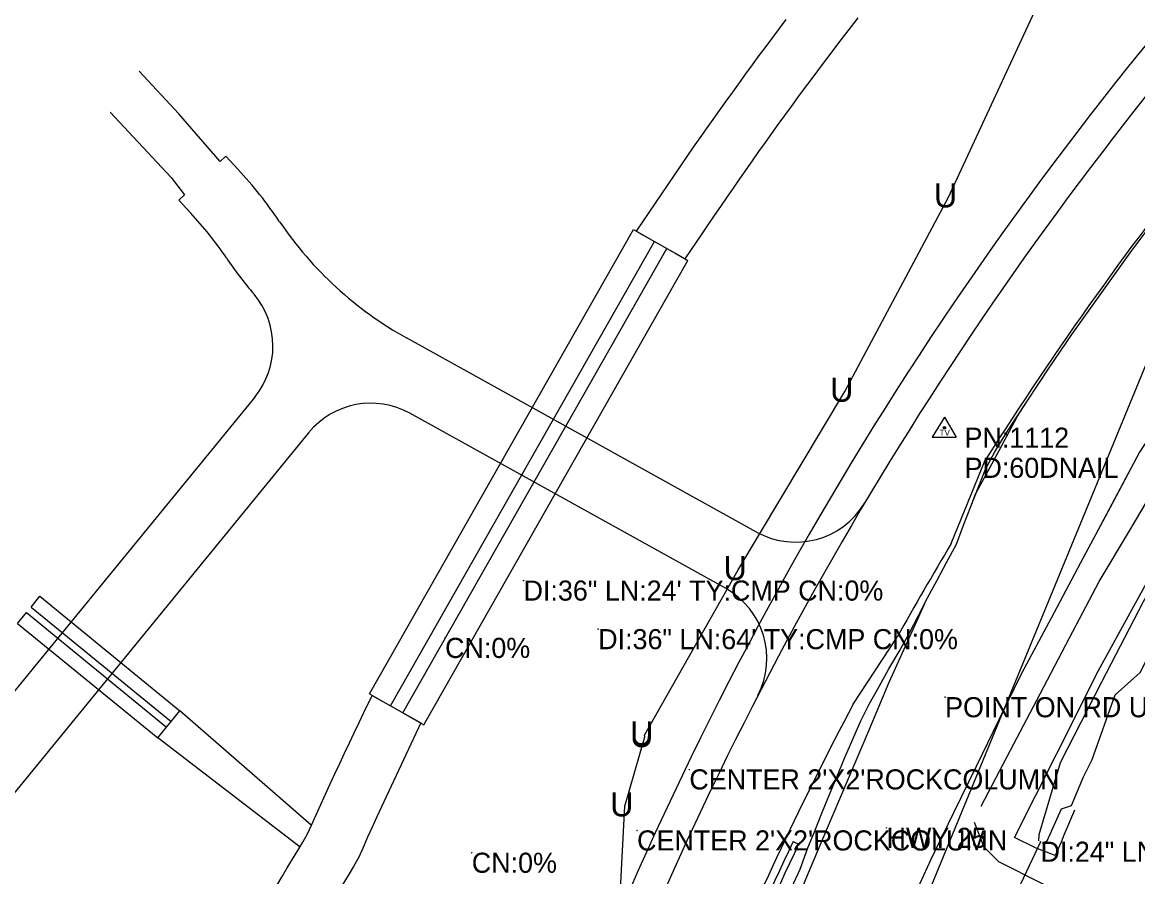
# Model space of a CAD drawing. Extents: x 1282810 to 1284464, y 402460 to 405899.
# Drawn here: x 1283356.5 to 1283634, y 404254.3 to 404466.8 of the extents above; entities that cross this region are included whole.
import ezdxf

# ---------------------------------------------------------------- set-up
doc = ezdxf.new("R2010")
doc.units = 0
for name, color, linetype in [('Default', 7, 'Continuous'), ('MOT_Drainage_Stage 2', 7, 'Continuous'), ('MOT_Driveway_Stage 2', 7, 'Continuous'), ('MOT_Proposed Road_Stage 2', 7, 'Continuous'), ('MOT_Shld_Stage 2', 7, 'Continuous'), ('MOT_Stage 1_Conc Ditch Paving', 7, 'Continuous'), ('MOT_Stage 2_Retaining Wall', 7, 'Continuous'), ('R_Conc Ditch Paving', 7, 'Continuous'), ('R_Drainage', 7, 'Continuous'), ('S_BASELINE', 7, 'Continuous'), ('S_CROSS_DRAIN', 7, 'Continuous'), ('S_CROSS_DRAIN_ANNOT', 7, 'Continuous'), ('S_DITCHLINE', 7, 'Continuous'), ('S_DRG_PT_SYM', 7, 'Continuous'), ('S_EDGE_CONCRETE', 7, 'Continuous'), ('S_EDGE_PAVEMENT', 7, 'Continuous'), ('S_MISC_STRUCTURES_ANNOT', 7, 'Continuous'), ('S_MSC_PT_SYM', 7, 'Continuous'), ('S_SECONDARY_CTL', 7, 'Continuous'), ('S_SECONDARY_CTL_ANNOT', 7, 'Continuous'), ('S_SHOULDER', 7, 'Continuous'), ('S_SURVEY_TEXT_ANNOT', 7, 'Continuous'), ('S_UNDERGROUND_CABLE', 7, 'Continuous'), ('S_UTL_PT_SYM', 7, 'Continuous')]:
    doc.layers.add(name, color=color, linetype=linetype)

msp = doc.modelspace()

# ---------------------------------------------------------------- linework, layer by layer
at = {"layer": 'MOT_Drainage_Stage 2'}
for p, q in [((1283442.9, 404299.75), (1283508.57, 404415.27)), ((1283508.57, 404415.27), (1283513.78, 404412.3)), ((1283448.12, 404296.78), (1283513.78, 404412.3)), ((1283451.16, 404295.05), (1283516.82, 404410.57)), ((1283516.82, 404410.57), (1283518.5, 404409.62)), ((1283518.79, 404409.46), (1283522.04, 404407.61)), ((1283456.38, 404292.09), (1283522.04, 404407.61)), ((1283442.9, 404299.75), (1283448.12, 404296.78)), ((1283451.16, 404295.05), (1283456.38, 404292.09))]:
    msp.add_line(p, q, dxfattribs=at)
at = {"layer": 'MOT_Driveway_Stage 2'}
for p, q in [((1283407.12, 404433.51), (1283405.74, 404432.23)), ((1283410.13, 404430.28), (1283407.12, 404433.51)), ((1283396.86, 404423.96), (1283395.41, 404422.62)), ((1283398.41, 404419.39), (1283395.41, 404422.62)), ((1283539.17, 404340.02), (1283452.1, 404388.31)), ((1283414.32, 404373.62), (1283274.79, 404202.97)), ((1283531.41, 404326.02), (1283452.91, 404369.57)), ((1283427.73, 404364.74), (1283287.18, 404192.85))]:
    msp.add_line(p, q, dxfattribs=at)
for centre, radius, start, end in [((1283331.05, 404356.72), 108, 34.0718, 42.9327), ((1283331.05, 404356.72), 92, 34.0718, 42.9327), ((1283496.72, 404468.77), 92, 214.0718, 240.9844), ((1283496.72, 404468.77), 108, 214.0718, 220.1219), ((1283398.84, 404386.28), 20, 320.7283, 40.1219), ((1283443.21, 404352.08), 20, 60.9844, 140.7283), ((1283548.87, 404357.51), 20, 240.9844, 329.2507), ((1283521.71, 404308.53), 20, 332.7181, 60.9844)]:
    msp.add_arc(centre, radius, start, end, dxfattribs=at)
at = {"layer": 'MOT_Proposed Road_Stage 2'}
for p, q in [((1283587.59, 404337.18), (1283596.03, 404357.88)), ((1283563.16, 404297.18), (1283574.13, 404313.88))]:
    msp.add_line(p, q, dxfattribs=at)
msp.add_lwpolyline([(1283718.07, 404476.36), (1283708.96, 404465.16), (1283699.85, 404453.97), (1283691.43, 404442.7), (1283683.01, 404431.44), (1283674.6, 404420.17), (1283666.18, 404408.91), (1283658.24, 404396.65), (1283650.31, 404384.4), (1283642.37, 404372.14), (1283634.44, 404359.89), (1283623.48, 404339.36)], dxfattribs=at)
for radius, start, end in [(905.47, 138.45801, 157.33333), (885.47, 141.27466, 147.66939), (881.81, 149.09939, 150.84794), (883.47, 152.14026, 157.33333)]:
    msp.add_arc((1284344.24, 403884.33), radius, start, end, dxfattribs=at)
at = {"layer": 'MOT_Shld_Stage 2'}
msp.add_arc((1284344.24, 403884.33), 913.47, 136.3373, 157.33333, dxfattribs=at)
at = {"layer": 'MOT_Stage 1_Conc Ditch Paving'}
for p, q in [((1283509.17, 404414.92), (1283521.39, 404407.98)), ((1283443.54, 404299.39), (1283455.61, 404292.52))]:
    msp.add_line(p, q, dxfattribs=at)
for points in [[(1283546.46, 404467.54), (1283544.77, 404465.3), (1283543.09, 404463.06), (1283541.42, 404460.81), (1283539.75, 404458.56), (1283538.08, 404456.3), (1283536.43, 404454.04), (1283534.78, 404451.77), (1283533.13, 404449.5), (1283531.5, 404447.22), (1283529.87, 404444.94), (1283528.24, 404442.65), (1283526.62, 404440.36), (1283525.01, 404438.07), (1283523.41, 404435.77), (1283521.81, 404433.46), (1283520.21, 404431.16), (1283518.63, 404428.85), (1283517.04, 404426.53), (1283515.46, 404424.21), (1283509.17, 404414.92)], [(1283521.39, 404407.98), (1283525.58, 404414.19), (1283527.13, 404416.48), (1283528.69, 404418.76), (1283530.25, 404421.05), (1283531.82, 404423.33), (1283533.39, 404425.61), (1283534.97, 404427.88), (1283536.55, 404430.15), (1283538.14, 404432.41), (1283539.74, 404434.67), (1283541.34, 404436.92), (1283542.95, 404439.17), (1283544.56, 404441.41), (1283546.18, 404443.65), (1283547.81, 404445.89), (1283549.44, 404448.12), (1283551.08, 404450.34), (1283552.73, 404452.56), (1283554.38, 404454.78), (1283556.04, 404456.99), (1283557.7, 404459.2), (1283559.37, 404461.4), (1283561.05, 404463.6), (1283562.73, 404465.79), (1283564.42, 404467.98)], [(1283419.78, 404252.12), (1283421.1, 404254.28), (1283422.42, 404256.44), (1283423.74, 404258.6), (1283425.05, 404260.76), (1283426.32, 404262.83), (1283427.4, 404264.9), (1283428.41, 404267.11), (1283429.57, 404269.67), (1283430.74, 404272.23), (1283431.91, 404274.79), (1283433.09, 404277.34), (1283434.27, 404279.9), (1283435.46, 404282.45), (1283436.66, 404284.99), (1283437.86, 404287.54), (1283439.06, 404290.08), (1283440.27, 404292.61), (1283441.49, 404295.15), (1283443.54, 404299.39)], [(1283455.61, 404292.52), (1283447.05, 404274.18), (1283445.88, 404271.66), (1283444.71, 404269.14), (1283443.56, 404266.61), (1283442.4, 404264.08), (1283441.26, 404261.55), (1283440.17, 404259.17), (1283438.92, 404256.79), (1283437.56, 404254.55), (1283436.24, 404252.39)]]:
    msp.add_lwpolyline(points, dxfattribs=at)
at = {"layer": 'MOT_Stage 2_Retaining Wall'}
msp.add_line((1283548.24, 404262.99), (1283549.59, 404262.34), dxfattribs=at)
for radius in [881.47, 879.97]:
    msp.add_arc((1284344.24, 403884.33), radius, 154.55939, 157.33333, dxfattribs=at)
at = {"layer": 'R_Conc Ditch Paving'}
for p, q in [((1283428.39, 404267.07), (1283395.71, 404295.56)), ((1283392.39, 404291.5), (1283393.49, 404292.85)), ((1283425.58, 404261.61), (1283390.17, 404288.79))]:
    msp.add_line(p, q, dxfattribs=at)
at = {"layer": 'R_Drainage'}
for p, q in [((1283358.66, 404321.34), (1283360.87, 404324.05)), ((1283360.87, 404324.05), (1283395.71, 404295.56)), ((1283355.33, 404317.27), (1283357.55, 404319.98)), ((1283357.55, 404319.98), (1283392.39, 404291.5)), ((1283358.66, 404321.34), (1283393.49, 404292.85)), ((1283355.33, 404317.27), (1283390.17, 404288.79)), ((1283393.49, 404292.85), (1283395.71, 404295.56)), ((1283390.17, 404288.79), (1283392.39, 404291.5))]:
    msp.add_line(p, q, dxfattribs=at)
at = {"layer": 'S_BASELINE'}
msp.add_line((1283396.79, 403800.11), (1283700.58, 404538.68), dxfattribs=at)
at = {"layer": 'S_CROSS_DRAIN'}
msp.add_line((1283609.78, 404262.98), (1283595.99, 404233.83), dxfattribs=at)
at = {"layer": 'S_DITCHLINE'}
for points in [[(1283609.36, 404263.21), (1283609.41, 404264.74), (1283614.77, 404282.66), (1283625.07, 404302.72), (1283635.38, 404322.78), (1283642.15, 404334.45), (1283648.92, 404346.13), (1283655.69, 404357.8), (1283662.46, 404369.47), (1283670.31, 404381.63), (1283678.16, 404393.78), (1283686, 404405.93), (1283693.85, 404418.09), (1283702.42, 404428.99), (1283710.99, 404439.89), (1283719.56, 404450.8), (1283728.14, 404461.7), (1283737.59, 404472.54)], [(1283610.29, 404262.6), (1283611.47, 404263.21), (1283614.97, 404271.12), (1283617.46, 404271.95), (1283620.45, 404279.13), (1283622.59, 404283.42), (1283628.37, 404299.55), (1283634.55, 404305.06), (1283644.21, 404323.84), (1283653.88, 404342.62), (1283663.81, 404358.58), (1283673.75, 404374.54), (1283683.07, 404383.99), (1283693.03, 404405.26), (1283703.98, 404420.61), (1283715.07, 404431.72), (1283723.5, 404444.12), (1283731.94, 404456.53), (1283742.27, 404467.67)]]:
    msp.add_lwpolyline(points, dxfattribs=at)
at = {"layer": 'S_DRG_PT_SYM'}
for points in [[(1283481.19, 404327.96), (1283481.19, 404328.01), (1283481.19, 404327.96), (1283481.14, 404327.96), (1283481.19, 404327.96), (1283481.19, 404327.91), (1283481.19, 404327.96), (1283481.24, 404327.96)], [(1283461.66, 404313.69), (1283461.66, 404313.74), (1283461.66, 404313.69), (1283461.61, 404313.69), (1283461.66, 404313.69), (1283461.66, 404313.64), (1283461.66, 404313.69), (1283461.71, 404313.69)], [(1283499.75, 404315.87), (1283499.75, 404315.92), (1283499.75, 404315.87), (1283499.7, 404315.87), (1283499.75, 404315.87), (1283499.75, 404315.82), (1283499.75, 404315.87), (1283499.8, 404315.87)], [(1283609.78, 404262.98), (1283609.78, 404263.03), (1283609.78, 404262.98), (1283609.73, 404262.98), (1283609.78, 404262.98), (1283609.78, 404262.93), (1283609.78, 404262.98), (1283609.83, 404262.98)], [(1283468.31, 404260.24), (1283468.31, 404260.29), (1283468.31, 404260.24), (1283468.26, 404260.24), (1283468.31, 404260.24), (1283468.31, 404260.19), (1283468.31, 404260.24), (1283468.36, 404260.24)]]:
    msp.add_lwpolyline(points, dxfattribs=at)
at = {"layer": 'S_EDGE_CONCRETE'}
msp.add_lwpolyline([(1283618.25, 404270.79), (1283615.62, 404264.61), (1283614.91, 404262.89), (1283613.43, 404259.58), (1283608.69, 404261.34), (1283603.27, 404264.04), (1283613.73, 404284.79), (1283624.19, 404305.55), (1283635.7, 404326.58), (1283647.2, 404347.61), (1283653.8, 404358.29), (1283660.4, 404368.97), (1283667, 404379.65), (1283673.6, 404390.33), (1283681.18, 404401.41), (1283688.76, 404412.48), (1283696.34, 404423.56), (1283703.92, 404434.64), (1283719.6, 404453.87), (1283735.28, 404473.1)], dxfattribs=at)
at = {"layer": 'S_EDGE_PAVEMENT'}
for points in [[(1283405.74, 404432.23), (1283395.47, 404444.08), (1283385.55, 404454.66)], [(1283378.38, 404444.49), (1283393.51, 404428.27), (1283396.86, 404423.96)], [(1283603.85, 404368.64), (1283606.42, 404372.59), (1283609.17, 404376.76), (1283611.96, 404380.9), (1283614.76, 404385.04), (1283617.6, 404389.15), (1283620.47, 404393.24), (1283623.35, 404397.32), (1283626.24, 404401.4), (1283629.16, 404405.45), (1283632.11, 404409.48), (1283635.09, 404413.5), (1283638.09, 404417.49), (1283641.14, 404421.45), (1283644.2, 404425.39), (1283647.29, 404429.32), (1283648.41, 404430.76)], [(1283603.85, 404368.64), (1283598.14, 404357.93), (1283593.73, 404349.67)], [(1283634.44, 404359.89), (1283627.09, 404346.13), (1283619.74, 404332.37), (1283612.4, 404318.61), (1283605.05, 404304.85), (1283599.42, 404293.28), (1283593.79, 404281.72), (1283588.16, 404270.15), (1283582.53, 404258.59), (1283576.15, 404244.59), (1283569.76, 404230.6), (1283563.51, 404216.22), (1283557.25, 404201.83), (1283551, 404187.45), (1283544.75, 404173.06), (1283538.9, 404159.19), (1283533.05, 404145.32), (1283527.2, 404131.45), (1283521.35, 404117.58), (1283514.89, 404102.6), (1283508.43, 404087.61), (1283501.97, 404072.63), (1283495.51, 404057.64)], [(1283580.91, 404322.16), (1283581.69, 404323.67), (1283584.04, 404328.08), (1283586.43, 404332.47), (1283588.86, 404337.04), (1283590.63, 404341.72), (1283592.43, 404346.38), (1283593.73, 404349.67)], [(1283580.91, 404322.16), (1283572.08, 404302.57), (1283566.88, 404290.31), (1283561.68, 404278.06), (1283556.49, 404265.8), (1283551.29, 404253.55), (1283545.42, 404239.1), (1283539.55, 404224.64), (1283533.68, 404210.19), (1283527.81, 404195.74), (1283522.03, 404181.72), (1283516.25, 404167.7), (1283510.47, 404153.68), (1283504.7, 404139.66), (1283498.96, 404125.92), (1283493.22, 404112.18), (1283487.49, 404098.44), (1283481.75, 404084.71), (1283475.3, 404069.12), (1283468.85, 404053.54)], [(1283593.24, 404267.8), (1283595.7, 404261.72), (1283599.33, 404258.06), (1283610.19, 404252.56), (1283628.07, 404243.86), (1283641.66, 404237.19), (1283635.3, 404223.5), (1283614.86, 404231.99), (1283600.63, 404239.28), (1283592.76, 404242.6), (1283586.77, 404243.11), (1283580.86, 404240.13)]]:
    msp.add_lwpolyline(points, dxfattribs=at)
at = {"layer": 'S_MSC_PT_SYM'}
for points in [[(1283586.05, 404298.94), (1283586.05, 404298.99), (1283586.05, 404298.94), (1283586, 404298.94), (1283586.05, 404298.94), (1283586.05, 404298.89), (1283586.05, 404298.94), (1283586.1, 404298.94)], [(1283522.42, 404280.98), (1283522.42, 404281.03), (1283522.42, 404280.98), (1283522.37, 404280.98), (1283522.42, 404280.98), (1283522.42, 404280.93), (1283522.42, 404280.98), (1283522.47, 404280.98)], [(1283571.49, 404266.44), (1283571.49, 404266.49), (1283571.49, 404266.44), (1283571.44, 404266.44), (1283571.49, 404266.44), (1283571.49, 404266.39), (1283571.49, 404266.44), (1283571.54, 404266.44)], [(1283509.42, 404265.79), (1283509.42, 404265.84), (1283509.42, 404265.79), (1283509.37, 404265.79), (1283509.42, 404265.79), (1283509.42, 404265.74), (1283509.42, 404265.79), (1283509.47, 404265.79)]]:
    msp.add_lwpolyline(points, dxfattribs=at)
at = {"layer": 'S_SECONDARY_CTL'}
for p, q in [((1283585.88, 404368.61), (1283582.87, 404363.65)), ((1283585.88, 404368.61), (1283588.83, 404363.65)), ((1283582.87, 404363.65), (1283588.83, 404363.65))]:
    msp.add_line(p, q, dxfattribs=at)
for radius in [0.311, 0.183, 0.103]:
    msp.add_circle((1283585.88, 404366), radius, dxfattribs=at)
at = {"layer": 'S_SHOULDER'}
for points in [[(1283594.98, 404271.8), (1283602.33, 404285.78), (1283609.68, 404299.75), (1283617.03, 404313.73), (1283624.38, 404327.7), (1283632.14, 404340.73), (1283639.89, 404353.76), (1283647.64, 404366.78), (1283655.39, 404379.81), (1283664.59, 404393.03), (1283673.79, 404406.25), (1283682.99, 404419.46), (1283692.19, 404432.68), (1283701.44, 404444.15), (1283710.69, 404455.61), (1283719.93, 404467.08)], [(1283551.94, 404261.42), (1283553.53, 404265.46), (1283555.39, 404270.09), (1283557.27, 404274.7), (1283559.18, 404279.31), (1283561.11, 404283.9), (1283563.1, 404288.48), (1283565.09, 404293.05), (1283567.17, 404297.23), (1283569.62, 404301.61), (1283572.07, 404305.98), (1283574.62, 404310.28), (1283577.11, 404314.8), (1283579.39, 404319.24), (1283581.69, 404323.67), (1283584.04, 404328.08), (1283586.43, 404332.47), (1283588.86, 404337.04), (1283590.63, 404341.72), (1283592.43, 404346.38), (1283594.27, 404351.04), (1283596.13, 404355.68), (1283598.38, 404359.94), (1283601.02, 404364.18), (1283603.7, 404368.4), (1283606.42, 404372.59), (1283609.17, 404376.76), (1283611.96, 404380.9), (1283614.76, 404385.04), (1283617.6, 404389.15), (1283620.47, 404393.24), (1283623.35, 404397.32), (1283626.24, 404401.4), (1283629.16, 404405.45), (1283632.11, 404409.48), (1283635.09, 404413.5)], [(1283514.46, 404173.11), (1283516.62, 404178.28), (1283518.55, 404182.9), (1283520.48, 404187.51), (1283522.4, 404192.12), (1283524.33, 404196.74), (1283526.26, 404201.35), (1283528.18, 404205.97), (1283530.11, 404210.58), (1283532.04, 404215.19), (1283533.96, 404219.81), (1283535.89, 404224.4), (1283537.83, 404228.97), (1283539.79, 404233.53), (1283541.78, 404238.08), (1283543.79, 404242.61), (1283545.83, 404247.14), (1283547.9, 404251.65), (1283549.99, 404256.15), (1283551.94, 404261.42)]]:
    msp.add_lwpolyline(points, dxfattribs=at)
at = {"layer": 'S_UNDERGROUND_CABLE'}
for p, q in [((1283586.9, 404423.34), (1283613.96, 404481.66)), ((1283561.07, 404374.97), (1283586.9, 404423.34)), ((1283534.56, 404330.61), (1283561.07, 404374.97)), ((1283511.3, 404289.48), (1283534.56, 404330.61)), ((1283506.35, 404271.81), (1283511.32, 404289.06)), ((1283511.32, 404289.06), (1283511.3, 404289.48)), ((1283504.99, 404245.42), (1283506.35, 404271.81))]:
    msp.add_line(p, q, dxfattribs=at)
at = {"layer": 'S_UTL_PT_SYM'}
msp.add_lwpolyline([(1283586.05, 404298.94), (1283586.05, 404298.99), (1283586.05, 404298.94), (1283586, 404298.94), (1283586.05, 404298.94), (1283586.05, 404298.89), (1283586.05, 404298.94), (1283586.1, 404298.94)], dxfattribs=at)

# ---------------------------------------------------------------- texts
at = {"layer": 'Default'}
for p in [(1283583.27, 404420.79), (1283557.44, 404372.43), (1283530.93, 404328.07), (1283507.67, 404286.93), (1283507.69, 404286.52), (1283502.72, 404269.27)]:
    msp.add_text('U', height=6, rotation=360, dxfattribs=at).set_placement(p)
at = {"layer": 'S_CROSS_DRAIN_ANNOT'}
for s, p in [('DI:36" LN:24\' TY:CMP CN:0%', (1283481.19, 404322.96)), ('CN:0%', (1283461.66, 404308.69)), ('DI:36" LN:64\' TY:CMP CN:0%', (1283499.75, 404310.87)), ('DI:24" LN:32\' TY:CMP CN:0%', (1283609.78, 404257.98)), ('CN:0%', (1283468.31, 404255.24))]:
    msp.add_text(s, height=5, dxfattribs=at).set_placement(p)
at = {"layer": 'S_MISC_STRUCTURES_ANNOT'}
for p in [(1283522.42, 404275.98), (1283509.42, 404260.79)]:
    msp.add_text("CENTER 2'X2'ROCKCOLUMN", height=5, dxfattribs=at).set_placement(p)
at = {"layer": 'S_SECONDARY_CTL'}
msp.add_text('TV', height=1.5, rotation=360, dxfattribs=at).set_placement((1283584.68, 404363.99))
at = {"layer": 'S_SECONDARY_CTL_ANNOT'}
for s, p in [('PN:1112', (1283590.88, 404361)), ('PD:60DNAIL', (1283590.88, 404353.5))]:
    msp.add_text(s, height=5, dxfattribs=at).set_placement(p)
at = {"layer": 'S_SURVEY_TEXT_ANNOT'}
for s, p in [('POINT ON RD UNDER LWST LN', (1283586.05, 404293.94)), ('HWY 25', (1283571.49, 404261.44))]:
    msp.add_text(s, height=5, dxfattribs=at).set_placement(p)

doc.saveas('drawing.dxf')
